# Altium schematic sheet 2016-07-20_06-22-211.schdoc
size 281 x 111 mm; SheetNumber: 1; SheetTotal: 1
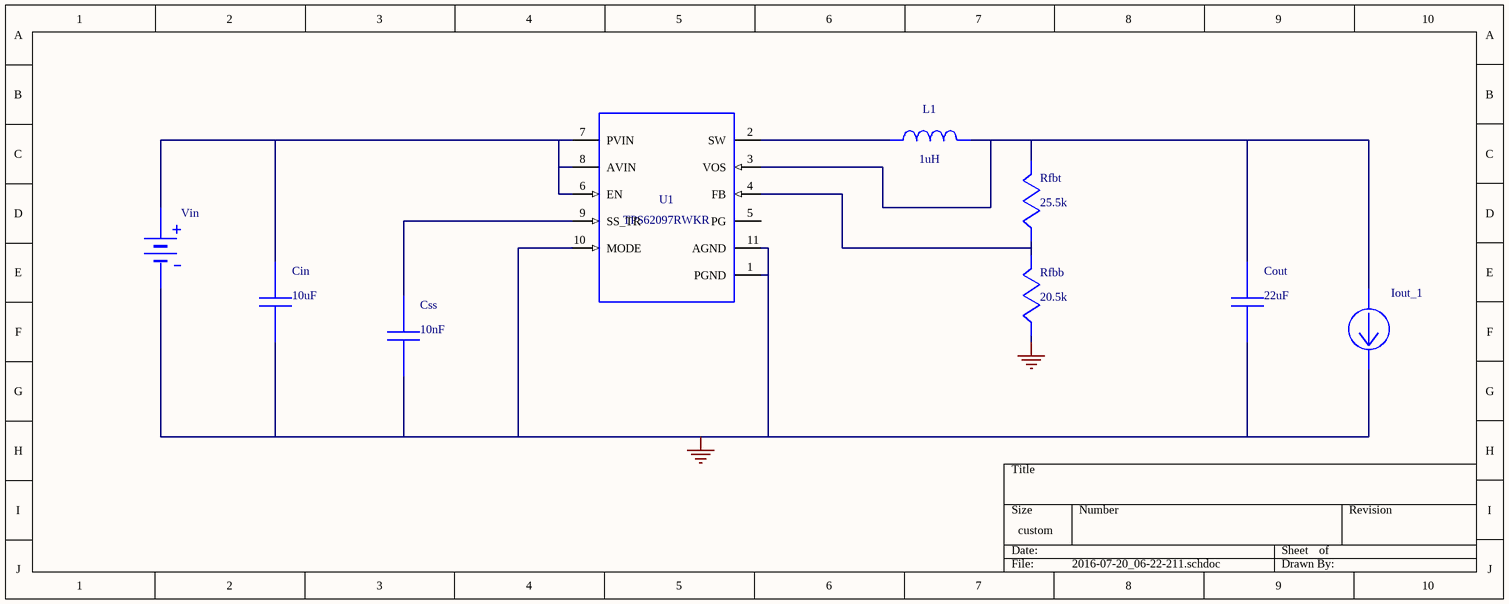
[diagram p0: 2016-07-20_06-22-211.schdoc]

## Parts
Cin  value 10uF  (hidden comment: GRM188R60J106ME47D)
Cout  value 22uF  (hidden comment: GRM21BC80G226ME39L)
Css  value 10nF  (hidden comment: GRM033R61A103KA01D)
Iout_1  WB_CURRENT_LOAD  (value not drawn)
L1  value 1uH  (hidden comment: SRN6045-1R0Y)
Rfbb  value 20.5k  (hidden comment: CRCW040220K5FKED)
Rfbt  value 25.5k  (hidden comment: CRCW040225K5FKED)
U1  TPS62097RWKR
Vin  WB_BATTERY  (value not drawn)

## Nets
0: Cin.2 Cout.2 Css.2 Iout_1.2(-) Rfbb.2 U1.1(PGND) U1.10(MODE) U1.11(AGND) Vin.2(-)
NetCin_1: Cin.1 U1.6(EN) U1.7(PVIN) U1.8(AVIN) Vin.1(+)
NetCout_1: Cout.1 Iout_1.1(+) L1.2 Rfbt.1 U1.3(VOS)
NetCss_1: Css.1 U1.9(SS_TR)
NetL1_1: L1.1 U1.2(SW)
NetRfbb_1: Rfbb.1 Rfbt.2 U1.4(FB)

Not connected (* = marked no-connect by the designer): U1 5(PG)

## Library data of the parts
Cin = GRM188R60J106ME47D: GRM188R60J106ME4; Manufacturer Name: MuRata
Cout = GRM21BC80G226ME39L: GRM21BC80G226ME3; Manufacturer Name: MuRata
Css = GRM033R61A103KA01D: GRM033R61A103KA0; Manufacturer Name: MuRata
L1 = SRN6045-1R0Y: Manufacturer Name: Bourns
Rfbb = CRCW040220K5FKED: Manufacturer Name: Vishay-Dale
Rfbt = CRCW040225K5FKED: Manufacturer Name: Vishay-Dale
U1 = TPS62097RWKR: Manufacturer Name: Texas Instruments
